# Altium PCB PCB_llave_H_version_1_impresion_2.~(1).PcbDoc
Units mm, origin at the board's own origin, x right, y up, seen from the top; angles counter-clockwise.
Board outline 85.85 x 71.63 mm, 2 copper layers (Top Layer, Bottom Layer); 118 components, 34 nets, 348 pads, 10 vias.
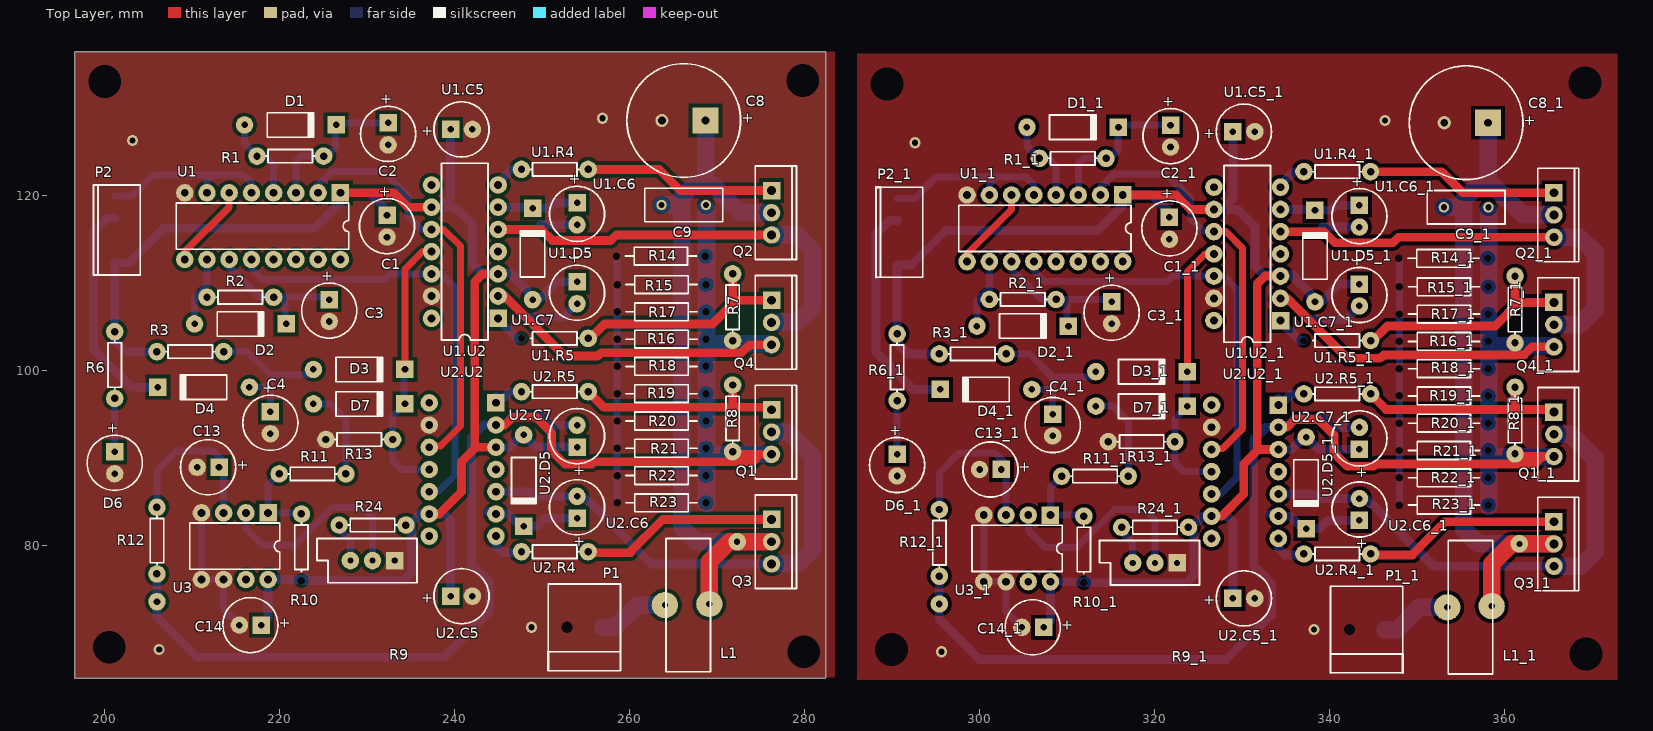
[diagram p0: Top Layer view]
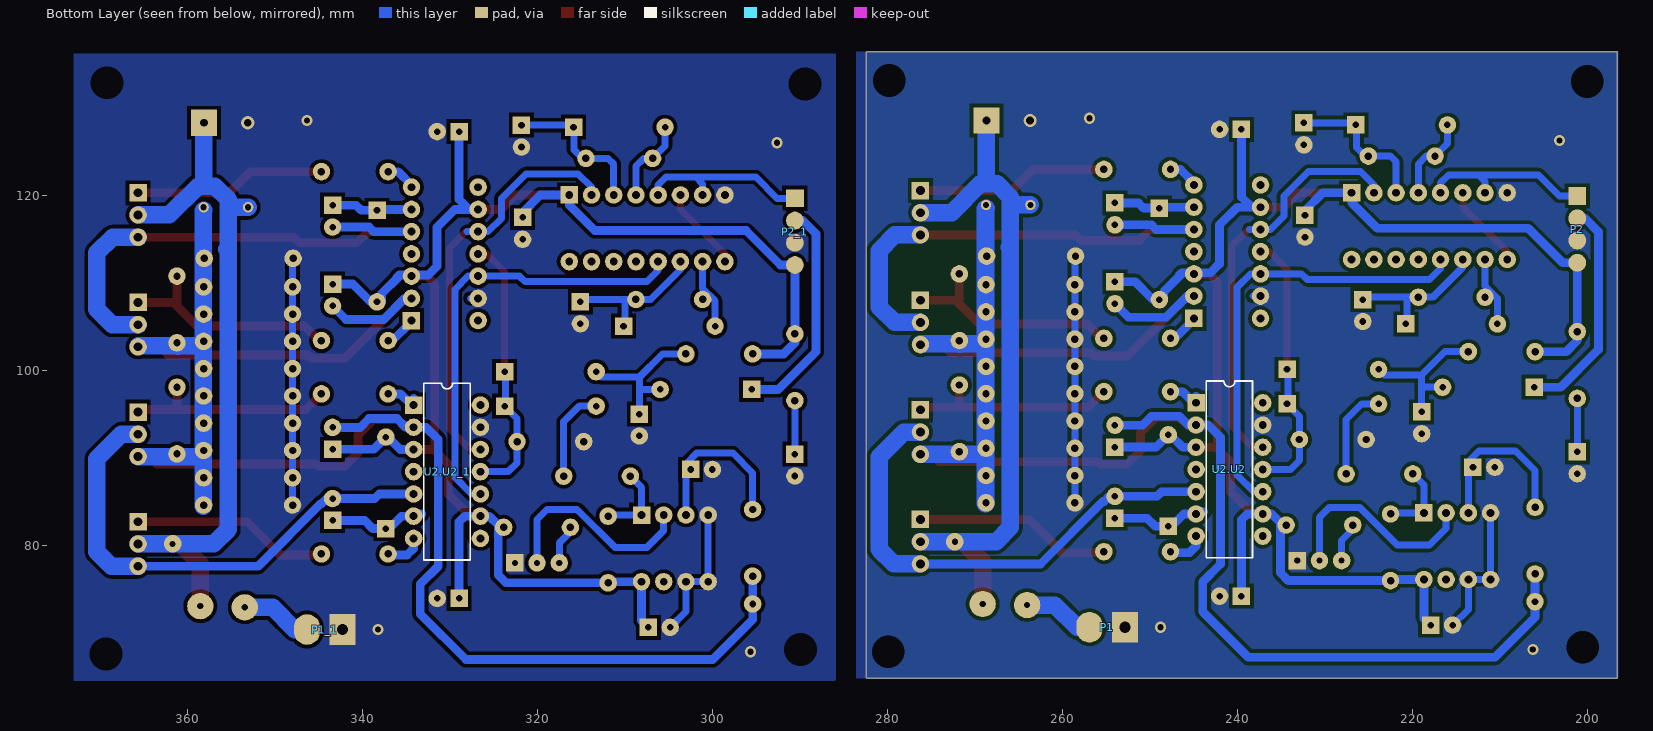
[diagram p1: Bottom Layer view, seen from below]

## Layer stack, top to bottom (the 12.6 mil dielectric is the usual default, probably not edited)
Top Layer: signal copper 0.0356
Dielectric: dielectric 0.32, FR-4, Dk 4.8
Bottom Layer: signal copper 0.0356

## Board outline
196.596,136.398 282.448,136.398 282.448,64.897 282.321,64.77 196.596,64.77

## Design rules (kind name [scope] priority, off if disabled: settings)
Clearance [All] p1: gap=0.4
ComponentClearance [All] p1: gap=0.254 collisioncheckmode=2 verticalgap=0.254
PlaneConnect [All] p1: planeconnectstyle=Direct reliefexpansion=0.508 reliefentries=4 reliefconductorwidth=0.254 reliefairgap=0.254
PolygonConnect [All] p1: connectstyle=Direct reliefconductorwidth=0.254 reliefentries=4 polygonreliefangle="90 Angle"
RoomDefinition U_4049_1 [InComponentClass('U_4049')] p1: confinementstyle=ConfineIn formatcopy=TRUE lockcomponents=FALSE outline 295.783,101.219 329.819,101.219 329.819,131.699 295.783,131.699
RoomDefinition Llave_H_esquema_1 [InComponentClass('Llave_H_esquema')] p2: confinementstyle=ConfineIn formatcopy=TRUE lockcomponents=FALSE outline 286.004,64.643 371.856,64.643 371.856,136.144 286.004,136.144
RoomDefinition U_Shutdown_1 [InComponentClass('U_Shutdown')] p3: confinementstyle=ConfineOut formatcopy=TRUE lockcomponents=FALSE outline 290.449,103.632 291.846,103.632 291.846,100.33 290.449,100.33
RoomDefinition U_INITShutdown_1 [InComponentClass('U_INITShutdown')] p4: confinementstyle=ConfineIn formatcopy=TRUE lockcomponents=FALSE outline 287.909,105.791 287.909,90.043 325.755,90.043 325.755,105.791
RoomDefinition U_Puente_H_1 [InComponentClass('U_Puente_H')] p5: confinementstyle=ConfineIn formatcopy=TRUE lockcomponents=FALSE outline 371.856,135.001 371.856,64.643 337.058,64.643 337.058,135.001
RoomDefinition U1_1 [InComponentClass('U1')] p6: confinementstyle=ConfineIn formatcopy=TRUE lockcomponents=FALSE outline 360.68,133.35 320.167,133.35 320.167,101.727 360.68,101.727
RoomDefinition U2_1 [InComponentClass('U2')] p7: confinementstyle=ConfineIn formatcopy=TRUE lockcomponents=FALSE outline 366.268,69.469 319.024,69.469 319.024,109.22 366.268,109.22
RoomDefinition U2 [InComponentClass('U2')] p8: confinementstyle=ConfineIn formatcopy=TRUE lockcomponents=FALSE outline 276.86,69.723 229.616,69.723 229.616,109.474 276.86,109.474
RoomDefinition U1 [InComponentClass('U1')] p9: confinementstyle=ConfineIn formatcopy=TRUE lockcomponents=FALSE outline 271.272,133.604 230.759,133.604 230.759,101.981 271.272,101.981
RoomDefinition U_Puente_H [InComponentClass('U_Puente_H')] p10: confinementstyle=ConfineIn formatcopy=TRUE lockcomponents=FALSE outline 282.448,135.255 282.448,64.897 247.65,64.897 247.65,135.255
RoomDefinition U_INITShutdown [InComponentClass('U_INITShutdown')] p11: confinementstyle=ConfineIn formatcopy=TRUE lockcomponents=FALSE outline 198.501,106.045 198.501,90.297 236.347,90.297 236.347,106.045
RoomDefinition U_Shutdown [InComponentClass('U_Shutdown')] p12: confinementstyle=ConfineOut formatcopy=TRUE lockcomponents=FALSE outline 201.041,103.886 202.438,103.886 202.438,100.584 201.041,100.584
RoomDefinition Llave_H_esquema [InComponentClass('Llave_H_esquema')] p13: confinementstyle=ConfineIn formatcopy=TRUE lockcomponents=FALSE outline 196.596,64.897 282.448,64.897 282.448,136.398 196.596,136.398
RoomDefinition U_4049 [InComponentClass('U_4049')] p14: confinementstyle=ConfineIn formatcopy=TRUE lockcomponents=FALSE outline 206.375,101.473 240.411,101.473 240.411,131.953 206.375,131.953
RoutingVias [All] p1: holewidth=0.711 width=1.27 viastyle="Through Hole" minholewidth=0.711 minwidth=1.27 maxholewidth=0.711 maxwidth=1.27
SolderMaskExpansion [All] p1: expansion=0.102
TestPointUsage [All] p1: valid=0 allowmultiple=FALSE
Testpoint [All] p1: side=15 testpointundercomponent=TRUE minsize=1.016 maxsize=2.54 preferedsize=1.524 minholesize=0 maxholesize=1.016 preferedholesize=0.813 testpointgrid=0.025 style=1023 order=0123456789
Width [All] p1: maxlimit=3 minlimit=0.8 preferedwidth=1
17 further rules are at their usual default settings.

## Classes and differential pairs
component class Llave_H_esquema: D6 P1 P2 R6
component class U_4049: C1 C2 C3 D1 D2 R1 R2 U1
component class U_Puente_H: C8 C9 L1 Q1 Q2 Q3 Q4 R7 R8
component class U_Shutdown: C13 C14 D7 R9 R10 R11 R12 R13 R14 R15 R16 R17 R18 R19 R20 R21 R22 R23 R24 U3
channel class IR2110: U1 U2
component class U_INITShutdown: C4 D3 D4 R3
component class U1: U1.C5 U1.C6 U1.C7 U1.D5 U1.R4 U1.R5 U1.U2 U_1_C5 U_1_C6 U_1_C7 U_1_D5 U_1_R4 U_1_R5 U_1_U2
component class U2: D5 U2.C5 U2.C6 U2.C7 U2.D5 U2.R4 U2.R5 U2.U2 U_2.D5 U_2_C5 U_2_C6 U_2_C7 U_2_R4 U_2_R5 U_2_U2

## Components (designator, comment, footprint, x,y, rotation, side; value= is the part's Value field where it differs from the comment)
C1 "Cap Pol1 0.1u" CAPPR2.5-6.3X5 232.283,116.459 r270 top
C1_1 "Cap Pol1 0.1u" CAPPR2.5-6.3X5 321.691,116.205 r270 top (schematic designator C1)
C2 "Cap Pol1" CAPPR2.5-6.3X5 232.41,127 r270 top
C2_1 "Cap Pol1" CAPPR2.5-6.3X5 321.818,126.746 r270 top (schematic designator C2)
C3 "Cap Pol1" CAPPR2.5-6.3X5 225.679,106.807 r270 top
C3_1 "Cap Pol1" CAPPR2.5-6.3X5 315.087,106.553 r270 top (schematic designator C3)
C4 "Cap Pol1 4.7u" CAPPR2.5-6.3X5 218.948,93.98 r270 top
C4_1 "Cap Pol1 4.7u" CAPPR2.5-6.3X5 308.356,93.726 r270 top (schematic designator C4)
C8 "Cap Pol1" CAPPR5-13X16 266.192,128.524 r180 top
C8_1 "Cap Pol1" CAPPR5-13X16 355.6,128.27 r180 top (schematic designator C8)
C9 "Cap" RAD-0.2 266.192,118.872 r180 top
C9_1 "Cap" RAD-0.2 355.6,118.618 r180 top (schematic designator C9)
C13 "Cap Pol1 4.7u" CAPPR2.5-6.3X5 211.836,88.9 r180 top
C13_1 "Cap Pol1 4.7u" CAPPR2.5-6.3X5 301.244,88.646 r180 top (schematic designator C13)
C14 "Cap Pol1 0.1u" CAPPR2.5-6.3X5 216.662,70.866 r180 top
C14_1 "Cap Pol1 0.1u" CAPPR2.5-6.3X5 306.07,70.612 r180 top (schematic designator C14)
D1 "Diode1" DO-204AL 221.234,128.016 r0 top
D1_1 "Diode1" DO-204AL 310.642,127.762 r0 top (schematic designator D1)
D2 "Diode1" DO-204AL 215.519,105.283 r0 top
D2_1 "Diode1" DO-204AL 304.927,105.029 r0 top (schematic designator D2)
D3 "Diode1" DO-204AL 229.108,100.076 r0 top
D3_1 "Diode1" DO-204AL 318.516,99.822 r0 top (schematic designator D3)
D4 "Diode1" DO-204AL 211.328,98.044 r180 top
D4_1 "Diode1" DO-204AL 300.736,97.79 r180 top (schematic designator D4)
D6 "LED0" CAPPR2.5-6.3X5 201.168,89.408 r270 top
D6_1 "LED0" CAPPR2.5-6.3X5 290.576,89.154 r270 top (schematic designator D6)
D7 "Diode1" DO-204AL 229.108,96.139 r0 top
D7_1 "Diode1" DO-204AL 318.516,95.885 r0 top (schematic designator D7)
L1 "Inductor" bobina_Choque 264.16,75.692 r270 top
L1_1 "Inductor" bobina_Choque 353.568,75.438 r270 top (schematic designator L1)
P1 "Header 2" pwheader1x2 255.016,70.612 r0 top
P1_1 "Header 2" pwheader1x2 344.424,70.358 r0 top (schematic designator P1)
P2 "Header 4" HDR1X5 193.548,112.268 r270 top
P2_1 "Header 4" HDR1X5 282.956,112.014 r270 top (schematic designator P2)
Q1 "IRF3205" TO-220AB 276.225,80.391 r270 top
Q1_1 "IRF3205" TO-220AB 365.633,80.137 r270 top (schematic designator Q1)
Q2 "IRF3205" TO-220AB 276.225,117.983 r270 top
Q2_1 "IRF3205" TO-220AB 365.633,117.729 r270 top (schematic designator Q2)
Q3 "IRF3205" TO-220AB 276.225,92.922 r270 top
Q3_1 "IRF3205" TO-220AB 365.633,92.668 r270 top (schematic designator Q3)
Q4 "IRF3205" TO-220AB 276.225,105.452 r270 top
Q4_1 "IRF3205" TO-220AB 365.633,105.198 r270 top (schematic designator Q4)
R1 "18k" AXIAL-0.3#1 221.234,124.46 r180 top
R1_1 "18k" AXIAL-0.3#1 310.642,124.206 r180 top (schematic designator R1)
R2 "18k" AXIAL-0.3#1 215.519,108.331 r0 top
R2_1 "18k" AXIAL-0.3#1 304.927,108.077 r0 top (schematic designator R2)
R3 "4.7k" AXIAL-0.3#1 209.804,102.108 r180 top
R3_1 "4.7k" AXIAL-0.3#1 299.212,101.854 r180 top (schematic designator R3)
R6 "1.2k" AXIAL-0.3#1 201.168,100.584 r90 top
R6_1 "1.2k" AXIAL-0.3#1 290.576,100.33 r90 top (schematic designator R6)
R7 "6.8" AXIAL-0.3#1 271.78,107.188 r90 top
R7_1 "6.8" AXIAL-0.3#1 361.188,106.934 r90 top (schematic designator R7)
R8 "6.8" AXIAL-0.3#2 271.78,94.488 r90 top
R8_1 "6.8" AXIAL-0.3#2 361.188,94.234 r90 top (schematic designator R8)
R9 "RPot" VR5 230.632,78.232 r180 top
R9_1 "RPot" VR5 320.04,77.978 r180 top (schematic designator R9)
R10 "3.3k" AXIAL-0.3#3 222.504,79.756 r270 top
R10_1 "3.3k" AXIAL-0.3#3 311.912,79.502 r270 top (schematic designator R10)
R11 "470" AXIAL-0.3#1 223.774,88.138 r0 top
R11_1 "470" AXIAL-0.3#1 313.182,87.884 r0 top (schematic designator R11)
R12 "6.8" AXIAL-0.3#1 205.994,80.518 r90 top locked
R12_1 "6.8" AXIAL-0.3#1 295.402,80.264 r90 top locked (schematic designator R12)
R13 "10k" AXIAL-0.3#1 229.108,92.075 r0 top
R13_1 "10k" AXIAL-0.3#1 318.516,91.821 r0 top (schematic designator R13)
R14 "Res2" AXIAL-0.4#1 263.585,113.03 r0 top
R14_1 "Res2" AXIAL-0.4#1 352.993,112.776 r0 top (schematic designator R14)
R15 "Res2" AXIAL-0.4#1 263.652,109.774 r0 top
R15_1 "Res2" AXIAL-0.4#1 353.06,109.52 r0 top (schematic designator R15)
R16 "Res2" AXIAL-0.4#1 263.652,106.657 r0 top
R16_1 "Res2" AXIAL-0.4#1 353.06,106.403 r0 top (schematic designator R16)
R17 "Res2" AXIAL-0.4#1 263.652,103.539 r0 top
R17_1 "Res2" AXIAL-0.4#1 353.06,103.285 r0 top (schematic designator R17)
R18 "Res2" AXIAL-0.4#1 263.652,100.422 r0 top
R18_1 "Res2" AXIAL-0.4#1 353.06,100.168 r0 top (schematic designator R18)
R19 "Res2" AXIAL-0.4#1 263.652,97.305 r0 top
R19_1 "Res2" AXIAL-0.4#1 353.06,97.051 r0 top (schematic designator R19)
R20 "Res2" AXIAL-0.4#2 263.652,94.188 r0 top
R20_1 "Res2" AXIAL-0.4#2 353.06,93.934 r0 top (schematic designator R20)
R21 "Res2" AXIAL-0.4#2 263.652,91.07 r0 top
R21_1 "Res2" AXIAL-0.4#2 353.06,90.816 r0 top (schematic designator R21)
R22 "Res2" AXIAL-0.4#2 263.652,87.953 r0 top
R22_1 "Res2" AXIAL-0.4#2 353.06,87.699 r0 top (schematic designator R22)
R23 "Res2" AXIAL-0.4#2 263.652,84.836 r0 top
R23_1 "Res2" AXIAL-0.4#2 353.06,84.582 r0 top (schematic designator R23)
R24 "6.8" AXIAL-0.3#1 230.632,82.296 r0 top
R24_1 "6.8" AXIAL-0.3#1 320.04,82.042 r0 top (schematic designator R24)
U1 "MC54HC4049J" 620-09 218.059,116.459 r180 top
U1.C5 "Cap Pol1 4.7u" CAPPR2.5-6.3X5 240.792,127.508 r0 top (schematic designator C5)
U1.C5_1 "Cap Pol1 4.7u" CAPPR2.5-6.3X5 330.2,127.254 r0 top (schematic designator C5)
U1.C6 "Cap Pol1" CAPPR2.5-6.3X5 254,117.856 r270 top (schematic designator C6)
U1.C6_1 "Cap Pol1" CAPPR2.5-6.3X5 343.408,117.602 r270 top (schematic designator C6)
U1.C7 "Cap Pol1" CAPPR2.5-6.3X5 254,108.839 r270 top (schematic designator C7)
U1.C7_1 "Cap Pol1" CAPPR2.5-6.3X5 343.408,108.585 r270 top (schematic designator C7)
U1.D5 "Diode" DO-204AL 248.92,113.284 r90 top (schematic designator D5)
U1.D5_1 "Diode" DO-204AL 338.328,113.03 r90 top (schematic designator D5)
U1.R4 "10" AXIAL-0.3#1 251.46,122.936 r0 top (schematic designator R4)
U1.R4_1 "10" AXIAL-0.3#1 340.868,122.682 r0 top (schematic designator R4)
U1.R5 "10" AXIAL-0.3#4 251.46,103.632 r0 top (schematic designator R5)
U1.R5_1 "10" AXIAL-0.3#4 340.868,103.378 r0 top (schematic designator R5)
U1.U2 "IR2110" PDIP14 241.173,113.538 r90 top (schematic designator U2)
U1.U2_1 "IR2110" PDIP14 330.581,113.284 r90 top (schematic designator U2)
U1_1 "MC54HC4049J" 620-09 307.467,116.205 r180 top (schematic designator U1)
U2.C5 "Cap Pol1 4.7u" CAPPR2.5-6.3X5 240.792,74.168 r0 top (schematic designator C5)
U2.C5_1 "Cap Pol1 4.7u" CAPPR2.5-6.3X5 330.2,73.914 r0 top (schematic designator C5)
U2.C6 "Cap Pol1" CAPPR2.5-6.3X5 254,84.328 r90 top (schematic designator C6)
U2.C6_1 "Cap Pol1" CAPPR2.5-6.3X5 343.408,84.074 r90 top (schematic designator C6)
U2.C7 "Cap Pol1" CAPPR2.5-6.3X5 254,92.456 r90 top (schematic designator C7)
U2.C7_1 "Cap Pol1" CAPPR2.5-6.3X5 343.408,92.202 r90 top (schematic designator C7)
U2.D5 "Diode" DO-204AL 247.904,87.376 r270 top (schematic designator D5)
U2.D5_1 "Diode" DO-204AL 337.312,87.122 r270 top (schematic designator D5)
U2.R4 "10" AXIAL-0.3#1 251.46,79.248 r0 top (schematic designator R4)
U2.R4_1 "10" AXIAL-0.3#1 340.868,78.994 r0 top (schematic designator R4)
U2.R5 "10" AXIAL-0.3#1 251.46,97.536 r0 top (schematic designator R5)
U2.R5_1 "10" AXIAL-0.3#1 340.868,97.282 r0 top (schematic designator R5)
U2.U2 "IR2110" PDIP14 240.919,88.646 r270 bottom (schematic designator U2)
U2.U2_1 "IR2110" PDIP14 330.327,88.392 r270 bottom (schematic designator U2)
U3 "LM393N" 626-05 214.884,79.883 r180 top
U3_1 "LM393N" 626-05 304.292,79.629 r180 top (schematic designator U3)

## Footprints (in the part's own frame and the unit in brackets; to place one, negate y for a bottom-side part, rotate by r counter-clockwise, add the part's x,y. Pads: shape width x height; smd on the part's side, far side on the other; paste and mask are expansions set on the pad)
620-09 [mm] "DIP; 16 Leads; Row Spacing 7.62 mm; Pitch 2.54 mm"
  rect 2x2 hole 0.9: 1(-8.89,-3.81)
  round 2 hole 0.9: 2(-6.35,-3.81) 3(-3.81,-3.81) 4(-1.27,-3.81) 5(1.27,-3.81) 6(3.81,-3.81) 7(6.35,-3.81) 8(8.89,-3.81) 9(8.89,3.81) 10(6.35,3.81) 11(3.81,3.81) 12(1.27,3.81) 13(-1.27,3.81) 14(-3.81,3.81) 15(-6.35,3.81) 16(-8.89,3.81)
  silkscreen extent -9.85,-2.65 9.85,2.65
626-05 [mm] "DIP; 8 Leads; Row Spacing 7.62 mm; Pitch 2.54 mm"
  rect 2x2 hole 0.9: 1(-3.81,-3.81)
  round 2 hole 0.9: 2(-1.27,-3.81) 3(1.27,-3.81) 4(3.81,-3.81) 5(3.81,3.81) 6(1.27,3.81) 7(-1.27,3.81) 8(-3.81,3.81)
  silkscreen extent -5.15,-2.65 5.15,2.65
AXIAL-0.3#1 [mm] "Resistor; 2 Leads"
  round 2 hole 0.85: 1(-3.81,0) 2(3.81,0)
  silkscreen extent -2.77,-0.76 2.77,0.76
AXIAL-0.3#2 [mm] "Resistor; 2 Leads"
  round 2 hole 0.85 paste+0 mask+0.102: 1(-3.81,0)
  round 2 hole 0.85: 2(3.81,0)
  silkscreen extent -2.77,-0.76 2.77,0.76
AXIAL-0.3#3 [mm] "Resistor; 2 Leads"
  round 2 hole 0.85: 1(-3.81,0)
  round 0 / inner round 0 / far side round 2 hole 0.85: 2(3.81,0)
  silkscreen extent -2.77,-0.76 2.77,0.76
AXIAL-0.3#4 [mm] "Resistor; 2 Leads"
  round 0 / inner round 0 / far side round 2 hole 0.85: 1(-3.81,0)
  round 2 hole 0.85: 2(3.81,0)
  silkscreen extent -2.77,-0.76 2.77,0.76
AXIAL-0.4#1 [mm] "Resistor; 2 Leads"
  round 0 / inner round 0 / far side round 2 hole 0.85: 1(-5.08,0) 2(5.08,0)
  silkscreen extent -4.06,-1.02 4.06,1.02
AXIAL-0.4#2 [mm] "Resistor; 2 Leads"
  round 0 / inner round 0 / far side round 2 hole 0.85: 1(-5.08,0)
  round 0 / inner round 0 / far side round 2 hole 0.85 unplated: 2(5.08,0)
  silkscreen extent -4.06,-1.02 4.06,1.02
bobina_Choque [mm]
  round 3 hole 0.7: 1(2.54,-0.127) 2(2.413,4.953)
  silkscreen extent -5.08,0 10.16,5.08
CAPPR2.5-6.3X5 [mm] "Capacitor, Electrolytic, Radial; Body 6.3 x 5 mm (Dia.xH typ); Pin Spacing 2.5 mm (typ)"
  rect 2x2 hole 0.75: 1(-1.25,0)
  round 2 hole 0.75: 2(1.25,0)
  silkscreen extent -3.15,-3.15 3.15,3.15
CAPPR5-13X16 [mm] "Capacitor, Electrolytic, Radial; Body 13 x 16 mm (Dia.xH typ); Pin Spacing 5 mm (typ)"
  rect 3x3 hole 0.9: 1(-2.5,0)
  round 1.5 hole 0.9: 2(2.5,0)
  silkscreen extent -6.5,-6.5 6.5,6.5
DO-204AL [mm] "Diode, Axial; Body 5.2 x 2.7 mm (LxDia. max), Lead Dia. 0.86 mm (max)"
  round 2 hole 0.75: 1(-5.23,0)
  rect 2x2 hole 0.75: 2(5.23,0)
  silkscreen extent -2.65,-1.4 2.75,1.4
HDR1X5 [mil]
  rect 80x80 smd far side: 1(-300,300)
  round 80 smd far side: 2(-200,300) 3(-100,300) 4(0,300)
  silkscreen extent -350,205 55,415
PDIP14 [mm] "DIP; 14 Leads; Row Spacing 7.62 mm; Pitch 2.54 mm"
  rect 2x2 hole 0.9: 1(-7.62,-3.81)
  round 2 hole 0.9: 2(-5.08,-3.81) 3(-2.54,-3.81) 4(0,-3.81) 5(2.54,-3.81) 6(5.08,-3.81) 7(7.62,-3.81) 8(7.62,3.81) 9(5.08,3.81) 10(2.54,3.81) 11(0,3.81) 12(-2.54,3.81) 13(-5.08,3.81) 14(-7.62,3.81)
  silkscreen extent -10.1,-2.65 10.1,2.65
pwheader1x2 [mm]
  round 0 / inner round 0 / far side rect 3x3.5 hole 1.3: 1(-2.159,0)
  oval 3x3.5 smd far side: 2(1.905,0)
  silkscreen extent -4.32,-4.95 3.94,4.95
RAD-0.2 [mm] "Jumper Wire; 2 Leads"
  round 1.2 hole 0.7: 1(-2.54,0) 2(2.54,0)
  silkscreen extent -4.44,-1.91 4.44,1.91
TO-220AB [mm] "TO, Thru-Hole, Vertical, Heatsink Mounted; 3 In-Line Leads; Pitch 2.54 mm"
  rect 2x2 hole 1: 1(-2.54,0)
  round 2 hole 1: 2(0,0) 3(2.54,0)
  silkscreen extent -5.35,-1.85 5.35,2.85
VR5 [mm] "Potentiometer; 3 Leads"
  rect 2x2 hole 0.7: 1(-2.54,0)
  round 2 hole 0.7: 2(2.54,0) 3(0,0)
  silkscreen extent -5.08,-2.54 6.35,2.54

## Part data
C1 C1_1 C4 C4_1 C14 C14_1 U1.C5 U1.C5_1 U2.C5 U2.C5_1: library part "Cap Pol1", "Polarized Capacitor (Radial)"
C2 C2_1 C3 C3_1 C8 C8_1 U1.C6 U1.C6_1 U1.C7 U1.C7_1 U2.C6 U2.C6_1 U2.C7 U2.C7_1: "Polarized Capacitor (Radial)"
C9 C9_1: "Capacitor"
C13 C13_1: library part "Cap Pol1", "Polarized 16V"
D1 D1_1 D2 D2_1: library part Diode, "1N4148"
D3 D3_1 D4 D4_1 D7 D7_1: library part Diode, "1n4148"
D6 D6_1: "Typical INFRARED GaAs LED"
P1 P1_1: "Header, 2-Pin"
P2 P2_1: "Header, 4-Pin"
Q1 Q1_1 Q2 Q2_1 Q3 Q3_1 Q4 Q4_1: "HEXFET Power MOSFET"
R1 R1_1 R2 R2_1 R3 R3_1 R6 R6_1 R7 R7_1 R8 R8_1 R24 R24_1 U1.R4 U1.R4_1 U1.R5 U1.R5_1 U2.R4 U2.R4_1 U2.R5 U2.R5_1: library part Res2, "Resistor"
R9 R9_1: "Potenciomentro multivuelta"
R10 R10_1 R11 R11_1 R12 R12_1 R13 R13_1: library part Res2, "metal film 1/2 W"
R14 R14_1 R15 R15_1 R16 R16_1 R17 R17_1 R18 R18_1 R19 R19_1 R20 R20_1 R21 R21_1 R22 R22_1 R23 R23_1: "metal film 1W"
U1 U1_1: "Hex Inverting Buffer/Logic-Level Down Converter"
U1.D5 U1.D5_1 U2.D5 U2.D5_1: "1N5819"
U1.U2 U1.U2_1 U2.U2 U2.U2_1: "High and Low Side Driver"
U3 U3_1: "Dual Comparator"

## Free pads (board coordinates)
  round 1.524 hole 3.75: 0(200.025,132.969) 0(200.533,68.326) 0(279.781,133.096) 0(279.908,67.818) 0(289.433,132.715) 0(289.941,68.072) 0(369.189,132.842) 0(369.316,67.564)
  round 2 hole 0.762: 1(205.994,73.533) 1(295.402,73.279)

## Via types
v1: diameter 1.27, hole 0.711, Top Layer to Bottom Layer, 8 vias
v2: diameter 2, hole 0.711, Top Layer to Bottom Layer, 2 vias

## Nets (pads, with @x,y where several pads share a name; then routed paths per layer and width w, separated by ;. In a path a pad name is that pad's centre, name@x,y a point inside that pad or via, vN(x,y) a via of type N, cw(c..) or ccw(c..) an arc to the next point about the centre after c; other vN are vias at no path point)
COMMON: C9.1 pad.1@205.994,73.533 Q3.3 Q4.3 R7.1 R8.1 R12.1 R14.2 R15.2 R16.2 R17.2 R18.2 R19.2 R20.2 R21.2 R22.2 R23.2 U1.C7.2 U1.U2.2 U2.C7.2 U2.U2.2 | length 218.7
  Top Layer w1: U2.U2.2 245.745,93.726 246.634,94.615 249.301,94.615 251.079,92.837 251.079,90.805 252.603,89.281 255.646,89.281 255.9,89.535 274.066,89.535 274.913,90.382 ; U1.U2.2 245.745,108.458 252.603,101.6 256.286,101.6 256.413,101.727 256.54,101.727 256.794,101.981 272.796,101.981 273.727,102.912 Q4.3 ; R8.1@271.78,90.382 Q3.3
  Bottom Layer w1: R12.1 205.994,71.755 210.566,67.183 238.76,67.183 243.967,72.39 243.967,75.819 241.935,77.851 241.935,92.329 243.332,93.726 245.633,93.726 246.629,94.722 249.829,94.722 250.845,93.706 U2.C7.2 ; U1.U2.2 245.745,108.458 248.158,106.045 252.456,106.045 U1.C7.2 ; R7.1@271.713,102.997 271.798,102.912 Q4.3
  Bottom Layer w2: C9.1@268.732,118.526 268.792,118.465 R23.2@268.792,84.709 ; R21.2@268.792,90.382 Q3.3 ; R17.2@268.792,103.031 Q4.3@276.191,103.031 ; R7.1@271.713,102.965 R7.1@271.78,103.031
GND: C1.2 C2.2 C3.2 C4.2 C8.2 C13.2 C14.2 D6.2 P1.1 P2.3 pad.0@200.025,132.969 pad.0@200.533,68.326 pad.0@279.781,133.096 pad.0@279.908,67.818 R9.1 R13.1 R14.1 R15.1 R16.1 R17.1 R18.1 R19.1 R20.1 R21.1 R22.1 R23.1 U1.8 U1.C5.2 U1.U2.13 U2.C5.2 U2.U2.13 U3.4 U3.5 U3.6 | length 45.2
  Top Layer w0.8: U3.5 211.094,76.093 U3.5@211.074,76.113 ; U3.6@213.594,76.093 U3.6
  Bottom Layer w0.8: U3.5 U3.4 ; U3.5@211.094,76.093 U3.6@213.594,76.093 ; U3.6 213.614,72.664 C14.2 ; U1.U2.13 U1.U2.13@238.252,108.458 ; R23.1 R14.1@258.572,112.963
  other v1: 206.248,68.072 248.793,70.612 203.2,126.238 256.921,128.778
HO1: Q2.1 U1.R4.2 | length 22
  Top Layer w1: U1.R4.2 263.398,122.936 265.811,120.523 Q2.1
HO2: Q1.1 U2.R4.2 | length 22
  Top Layer w1: U2.R4.2@255.905,79.121 260.096,79.121 ; 259.969,79.121 263.779,82.931 Q1.1
IN_SD: D4.2 P2.2 | length 25.6
  Bottom Layer w1: P2.2 200.279,117.348 198.755,115.824 198.755,102.362 203.073,98.044 D4.2
LO1: Q4.1 R7.2 U1.R5.2 | length 26.4
  Top Layer w1: U1.R5.2 255.524,103.632 257.175,105.283 269.494,105.283 272.203,107.992 Q4.1 ; R7.2@271.78,111.252 271.78,107.592 271.791,107.58
LO2: Q3.1 R8.2 U2.R5.2 | length 24.5
  Top Layer w1: U2.R5.2@255.778,97.536 255.778,97.028 257.048,95.758 275.929,95.758 Q3.1 ; R8.2@271.526,98.679 R8.2@271.78,98.425 ; 271.78,95.758 R8.2
MOTOR+: Q2.3 Q4.2 U1.C6.2 U1.U2.5 | length 58.6
  Top Layer w1: U1.U2.5 249.936,116.078 251.206,114.808 257.836,114.808 258.471,115.443 Q2.3
  Bottom Layer w1: U1.U2.5 249.301,116.078 249.829,116.606 U1.C6.2
  Bottom Layer w2: Q4.2 279.188,105.452 280.924,107.188 280.924,113.665 279.146,115.443 Q2.3
MOTOR-: Q1.3 Q3.2 U2.C6.2 U2.U2.5 | length 56.8
  Bottom Layer w1: U2.U2.5 248.666,86.106 249.194,85.578 254.655,85.578 255.255,84.978 255.382,84.978 262.509,77.851 Q1.3
  Bottom Layer w2: Q1.3 279.273,77.851 280.924,79.502 280.924,90.128 278.13,92.922 Q3.2
NetC2_1: C2.1 D1.2 R1.1 U1.3 | length 17.4
  Bottom Layer w0.8: U1.3 221.869,123.825 222.504,124.46 225.425,124.46 226.403,125.438 226.403,127.955 226.698,128.25 C2.1
NetC3_1: C3.1 D2.2 R2.2 U1.11 | length 17
  Bottom Layer w0.8: U1.11 214.249,111.76 217.678,108.331 225.405,108.331 C3.1 ; 220.599,108.331 220.599,105.433 D2.2
NetC4_1: C4.1 D3.1 D4.1 R3.1 | length 18.2
  Bottom Layer w0.8: R3.1 216.281,102.108 218.948,99.441 ; D4.1 218.948,98.044 ; C4.1 218.948,99.441 ; D3.1 223.243,99.441 218.948,99.441
NetC13_1: C13.1 R12.2 U3.3 | length 19.1
  Bottom Layer w0.8: R12.2 205.994,88.519 208.24,90.765 212.384,90.765 213.614,89.535 U3.3
NetD1_1: D1.1 R1.2 U1.4 | length 9.7
  Bottom Layer w0.8: D1.1 216.004,125.88 R1.2 218.44,124.46 219.329,123.571 U1.4
NetD2_1: D2.1 R2.1 U1.10 | length 8
  Bottom Layer w0.8: D2.1 210.289,108.181 211.709,109.601 U1.10
NetD6_1: D6.1 R6.1 | length 6.1
  Bottom Layer w0.8: D6.1 R6.1
NetD7_1: D7.1 R11.2 | length 10.7
  Bottom Layer w0.8: D7.1 225.806,96.139 227.584,94.361 R11.2
NetR9_2: R9.2 R24.1 | length 4.8
  Bottom Layer w0.8: R24.1@226.949,82.55 226.949,81.661 228.092,80.518 R9.2
NetR9_3: R9.3 U3.2 | length 24.3
  Bottom Layer w0.8: U3.2 216.154,81.915 218.059,80.01 221.742,80.01 226.06,84.328 229.489,84.328 230.632,83.185 R9.3
NetR10_1: R10.1 R11.1 U3.1 | length 9.5
  Bottom Layer w0.8: R11.1 218.694,86.868 U3.1 222.504,83.693 R10.1@223.012,83.185
NetU1.C6_1: U1.C6.1 U1.D5.2 U1.U2.6 | length 9.8
  Bottom Layer w1: U1.U2.6 248.308,118.618 248.412,118.514 250.721,118.514 251.313,119.106 U1.C6.1 ; U1.D5.2@248.943,118.872 U1.D5.2@249.301,118.514
NetU1.R4_1: U1.R4.1 U1.U2.7 | length 3.8
  Bottom Layer w1: U1.U2.7 244.983,121.412 246.507,122.936 U1.R4.1@247.904,122.936
NetU1.R5_1: U1.R5.1 U1.U2.1 | length 3.7
  Bottom Layer w1: U1.U2.1 244.983,105.791 247.142,103.632 U1.R5.1
NetU1_6: U1.6 U1.9 | length 9.9
  Top Layer w0.8: U1.9 209.169,113.538 214.249,118.618 U1.6
  Bottom Layer w0.8: U1.9 U1.9@209.169,112.776
NetU2.C6_1: U2.C6.1 U2.D5.2 U2.U2.6 | length 10.8
  Bottom Layer w1: U2.U2.6@243.84,83.82 U2.U2.6@244.602,83.82 ; U2.U2.6 246.126,83.566 U2.D5.2@247.673,82.019 ; U2.D5.2 249.405,82.146 250.337,83.078 U2.C6.1
NetU2.R4_1: U2.R4.1 U2.U2.7 | length 4.9
  Bottom Layer w1: U2.U2.7 244.729,79.883 245.491,79.121 U2.R4.1@248.158,79.121
NetU2.R5_1: U2.R5.1 U2.U2.1 | length 4.7
  Bottom Layer w1: U2.U2.1@244.729,97.028 U2.U2.1 244.983,96.266 246.253,97.536 U2.R5.1@248.158,97.536
PWM: P2.1 U1.5 U1.7 | length 20.5
  Bottom Layer w0.8: P2.1 203.2,119.888 205.613,122.301 215.9,122.301 216.789,121.412 U1.5 ; U1.7 211.709,121.539 212.471,122.301
SD: D3.2 D7.2 R13.2 U1.U2.11 U2.U2.11 | length 31.1
  Top Layer w0.8: D3.2 234.338,111.529 236.347,113.538 U1.U2.11
  Bottom Layer w0.8: D7.2@234.241,96.042 234.241,99.979 D3.2 ; D7.2 232.918,94.719 232.918,89.662 233.934,88.646 U2.U2.11
U1.HIN: U1.2 U1.U2.10 U2.U2.12 | length 48.9
  Top Layer w0.8: U2.U2.12@237.236,91.313 238.379,91.313 240.665,93.599 240.665,114.173 238.76,116.078 U1.U2.10
  Bottom Layer w0.8: U1.2 224.409,121.158 225.933,122.682 231.902,122.682 234.696,119.888 234.696,117.602 236.22,116.078 238.633,116.078
U1.LIN: U1.12 U1.U2.12 U2.U2.10 | length 50.9
  Bottom Layer w0.8: U1.12 216.789,111.633 218.059,110.363 232.029,110.363 232.664,110.998 238.506,110.998 240.03,109.474 240.03,88.011 238.125,86.106 U2.U2.10
VCC_MOTOR: L1.1 P1.2 | length 8.2
  Bottom Layer w2: P1.2 258.318,70.612 260.858,73.152 L1.1
VCC_MOTOR_FILTRADO: C8.1 C9.2 L1.2 Q1.2 Q2.2 | length 83.3
  Top Layer w2: L1.2 269.113,78.105 271.399,80.391 Q1.2
  Bottom Layer w2: C9.2 265.811,118.872 265.938,118.745 ; 265.938,113.919 266.065,114.046 ; 268.692,121.579 C8.1 ; Q1.2 267.589,80.391 265.938,82.042 265.938,119.761 267.462,121.285 269.367,121.285 272.669,117.983 Q2.2
  other v2: 272.288,80.391
VDD: C1.1 C14.1 P2.4 R3.2 R6.2 R10.2 R24.2 U1.1 U1.C5.1 U1.C7.1 U1.D5.1 U1.U2.3 U1.U2.9 U2.C5.1 U2.C7.1 U2.D5.1 U2.U2.3 U2.U2.9 U3.8 | length 184.4
  Top Layer w0.8: C14.1 C14.1@217.912,71.481 ; U3.8@218.567,76.327 218.694,76.2 U3.8
  Top Layer w1: U1.1 233.045,120.269 234.696,118.618 U1.U2.9 ; U2.U2.9 238.252,83.566 240.792,86.106 240.792,89.535 242.443,91.186 U2.U2.3 ; 242.316,91.059 242.316,110.109 243.205,110.998 U1.U2.3
  Bottom Layer w0.8: R10.2@222.994,76.309 R10.2@223.012,76.292 ; C1.1 C1.1@232.283,118.11
  Bottom Layer w1: R3.2 202.438,102.108 201.168,103.378 P2.4 202.819,112.268 206.756,116.205 224.028,116.205 226.949,119.126 U1.1 230.251,120.269 232.283,118.237 C1.1 ; C14.1 218.694,71.648 U3.8 R10.2@222.758,76.073 ; R10.2 234.188,75.946 235.077,76.835 235.077,82.55 236.093,83.566 238.887,83.566 239.542,82.911 U2.C5.1 ; U1.U2.9 240.03,118.618 242.062,116.586 242.062,112.141 243.078,111.125 246.38,111.125 246.634,110.871 ; 238.379,118.618 239.542,119.781 U1.C5.1 ; U2.U2.3 246.253,91.186 U2.D5.1@247.546,92.479 ; 246.38,110.998 248.412,108.966 U1.D5.1@248.412,108.054 ; U2.D5.1 247.904,92.583 249.281,91.206 U2.C7.1 ; U1.D5.1 249.659,108.054 251.694,110.089 U1.C7.1
pads on no net: C1_1.1 C1_1.2 C2_1.1 C2_1.2 C3_1.1 C3_1.2 C4_1.1 C4_1.2 C8_1.1 C8_1.2 C9_1.1 C9_1.2 C13_1.1 C13_1.2 C14_1.1 C14_1.2 D1_1.1 D1_1.2 D2_1.1 D2_1.2 D3_1.1 D3_1.2 D4_1.1 D4_1.2 D6_1.1 D6_1.2 D7_1.1 D7_1.2 L1_1.1 L1_1.2 P1_1.1 P1_1.2 P2_1.1 P2_1.2 P2_1.3 P2_1.4 Q1_1.1 Q1_1.2 Q1_1.3 Q2_1.1 Q2_1.2 Q2_1.3 Q3_1.1 Q3_1.2 Q3_1.3 Q4_1.1 Q4_1.2 Q4_1.3 R1_1.1 R1_1.2 R2_1.1 R2_1.2 R3_1.1 R3_1.2 R6_1.1 R6_1.2 R7_1.1 R7_1.2 R8_1.1 R8_1.2 R9_1.1 R9_1.2 R9_1.3 R10_1.1 R10_1.2 R11_1.1 R11_1.2 R12_1.1 R12_1.2 R13_1.1 R13_1.2 R14_1.1 R14_1.2 R15_1.1 R15_1.2 R16_1.1 R16_1.2 R17_1.1 R17_1.2 R18_1.1 R18_1.2 R19_1.1 R19_1.2 R20_1.1 R20_1.2 R21_1.1 R21_1.2 R22_1.1 R22_1.2 R23_1.1 R23_1.2 R24_1.1 R24_1.2 U1.13 U1.14 U1.15 U1.16 U1.C5_1.1 U1.C5_1.2 U1.C6_1.1 U1.C6_1.2 U1.C7_1.1 U1.C7_1.2 U1.D5_1.1 U1.D5_1.2 U1.R4_1.1 U1.R4_1.2 U1.R5_1.1 U1.R5_1.2 U1.U2.4 U1.U2.8 U1.U2.14 U1.U2_1.1 U1.U2_1.2 U1.U2_1.3 U1.U2_1.4 U1.U2_1.5 U1.U2_1.6 U1.U2_1.7 U1.U2_1.8 U1.U2_1.9 U1.U2_1.10 U1.U2_1.11 U1.U2_1.12 U1.U2_1.13 U1.U2_1.14 U1_1.1 U1_1.2 U1_1.3 U1_1.4 U1_1.5 U1_1.6 U1_1.7 U1_1.8 U1_1.9 U1_1.10 U1_1.11 U1_1.12 U1_1.13 U1_1.14 U1_1.15 U1_1.16 U2.C5_1.1 U2.C5_1.2 U2.C6_1.1 U2.C6_1.2 U2.C7_1.1 U2.C7_1.2 U2.D5_1.1 U2.D5_1.2 U2.R4_1.1 U2.R4_1.2 U2.R5_1.1 U2.R5_1.2 U2.U2.4 U2.U2.8 U2.U2.14 U2.U2_1.1 U2.U2_1.2 U2.U2_1.3 U2.U2_1.4 U2.U2_1.5 U2.U2_1.6 U2.U2_1.7 U2.U2_1.8 U2.U2_1.9 U2.U2_1.10 U2.U2_1.11 U2.U2_1.12 U2.U2_1.13 U2.U2_1.14 U3.7 U3_1.1 U3_1.2 U3_1.3 U3_1.4 U3_1.5 U3_1.6 U3_1.7 U3_1.8
copper on no net: | length 1119.2
  Top Layer w0.8: 298.577,112.395 298.577,113.284 303.657,118.364 303.657,120.015 ; 300.482,75.819 300.502,75.839 300.482,75.859 ; 303.002,75.839 303.022,75.819 ; 307.32,70.612 307.32,71.227 ; 307.975,76.073 308.102,75.946 308.102,75.819 ; 323.746,99.822 323.746,111.275 325.755,113.284 326.771,113.284 ; 326.644,91.059 327.787,91.059 330.073,93.345 330.073,113.919 328.168,115.824 326.771,115.824
  Top Layer w1: 316.357,120.015 322.453,120.015 324.104,118.364 326.771,118.364 ; 326.517,83.312 327.66,83.312 330.2,85.852 330.2,89.281 331.851,90.932 334.137,90.932 ; 331.724,90.805 331.724,109.855 332.613,110.744 334.391,110.744 ; 334.137,93.472 335.153,93.472 336.042,94.361 338.709,94.361 340.487,92.583 340.487,90.551 342.011,89.027 345.054,89.027 345.308,89.281 363.474,89.281 364.321,90.128 ; 334.391,108.204 335.153,108.204 342.011,101.346 345.694,101.346 345.821,101.473 345.948,101.473 346.202,101.727 362.204,101.727 363.135,102.658 365.633,102.658 ; 334.391,115.824 339.344,115.824 340.614,114.554 347.244,114.554 347.879,115.189 365.633,115.189 ; 344.678,103.378 344.932,103.378 346.583,105.029 358.902,105.029 361.611,107.738 365.633,107.738 ; 344.678,122.682 352.806,122.682 355.219,120.269 365.633,120.269 ; 345.186,97.282 345.186,96.774 346.456,95.504 365.337,95.504 365.633,95.208 ; 345.313,78.867 349.504,78.867 ; 349.377,78.867 353.187,82.677 365.633,82.677 ; 360.934,98.425 361.188,98.171 ; 361.188,90.128 365.633,90.128 ; 361.188,95.504 361.188,98.044 ; 361.188,110.998 361.188,107.338 361.199,107.326
  Top Layer w2: 358.521,73.025 358.521,77.851 360.807,80.137 365.633,80.137
  Bottom Layer w0.8: 290.576,90.404 290.576,96.52 ; 290.576,119.634 292.608,119.634 295.021,122.047 305.308,122.047 306.197,121.158 306.197,120.015 ; 295.402,84.074 295.402,88.265 297.648,90.511 301.792,90.511 303.022,89.281 303.022,83.439 ; 298.577,112.395 298.577,112.522 ; 299.697,105.029 299.697,107.927 301.117,109.347 301.117,112.395 ; 300.482,75.819 300.482,83.439 ; 300.502,75.839 303.002,75.839 ; 301.117,120.015 301.117,121.285 301.879,122.047 ; 303.022,75.819 303.022,72.41 304.82,70.612 ; 303.022,101.854 305.689,101.854 308.356,99.187 ; 303.657,112.395 303.657,111.506 307.086,108.077 314.813,108.077 315.087,107.803 ; 305.412,127.762 305.412,125.626 306.832,124.206 307.848,124.206 308.737,123.317 308.737,120.015 ; 305.562,83.439 305.562,81.661 307.467,79.756 311.15,79.756 315.468,84.074 318.897,84.074 320.04,82.931 320.04,77.978 ; 305.966,97.79 308.356,97.79 ; 306.197,112.395 306.197,111.379 307.467,110.109 321.437,110.109 322.072,110.744 327.914,110.744 329.438,109.22 329.438,87.757 327.533,85.852 326.517,85.852 ; 308.356,94.976 308.356,99.187 ; 309.372,87.884 308.102,86.614 308.102,83.439 311.912,83.439 312.42,82.931 ; 310.007,108.077 310.007,105.179 310.157,105.029 ; 311.277,120.015 311.277,123.571 311.912,124.206 314.833,124.206 315.811,125.184 315.811,127.701 316.106,127.996 321.818,127.996 ; 312.402,76.055 312.42,76.038 ; 313.286,95.885 315.214,95.885 316.992,94.107 316.992,87.884 ; 313.286,99.822 312.651,99.187 308.356,99.187 ; 313.817,120.015 313.817,120.904 315.341,122.428 321.31,122.428 324.104,119.634 324.104,117.348 325.628,115.824 328.041,115.824 ; 316.357,82.296 316.357,81.407 317.5,80.264 317.5,77.978 ; 321.691,117.455 321.691,117.856 ; 323.649,95.788 323.649,99.725 323.746,99.822 ; 323.746,95.885 322.326,94.465 322.326,89.408 323.342,88.392 326.517,88.392 ; 326.771,108.204 327.66,108.204 ; 347.98,84.582 347.98,112.709
  Bottom Layer w1: 290.576,117.094 289.687,117.094 288.163,115.57 288.163,102.108 292.481,97.79 295.506,97.79 ; 295.402,76.454 295.402,71.501 299.974,66.929 328.168,66.929 333.375,72.136 333.375,75.565 331.343,77.597 331.343,92.075 332.74,93.472 335.041,93.472 336.037,94.468 339.237,94.468 340.253,93.452 343.408,93.452 ; 295.402,101.854 291.846,101.854 290.576,103.124 290.576,112.014 292.227,112.014 296.164,115.951 313.436,115.951 316.357,118.872 316.357,120.015 319.659,120.015 321.691,117.983 321.691,117.455 ; 307.32,70.612 308.102,71.394 308.102,75.819 312.166,75.819 ; 311.912,75.692 323.596,75.692 324.485,76.581 324.485,82.296 325.501,83.312 328.295,83.312 328.95,82.657 328.95,73.914 ; 326.771,118.364 329.438,118.364 331.47,116.332 331.47,111.887 332.486,110.871 335.788,110.871 336.042,110.617 ; 327.787,118.364 328.95,119.527 328.95,127.254 ; 333.248,83.566 334.01,83.566 ; 334.137,80.772 334.137,79.629 334.899,78.867 337.566,78.867 ; 334.137,83.312 335.534,83.312 337.081,81.765 ; 334.137,85.852 338.074,85.852 338.602,85.324 344.063,85.324 344.663,84.724 344.79,84.724 351.917,77.597 365.633,77.597 ; 334.137,90.932 335.661,90.932 336.954,92.225 ; 334.137,96.774 334.137,96.012 334.391,96.012 335.661,97.282 337.566,97.282 ; 334.391,105.664 334.391,105.537 336.55,103.378 337.058,103.378 ; 334.391,108.204 335.153,108.204 337.566,105.791 341.864,105.791 343.408,107.335 ; 334.391,115.824 338.709,115.824 339.237,116.352 343.408,116.352 ; 334.391,118.364 337.716,118.364 337.82,118.26 340.129,118.26 340.721,118.852 343.408,118.852 ; 334.391,120.904 334.391,121.158 335.915,122.682 337.312,122.682 ; 335.788,110.744 337.82,108.712 337.82,107.8 ; 337.312,81.892 338.813,81.892 339.745,82.824 343.408,82.824 ; 337.312,92.352 337.312,92.329 338.689,90.952 343.408,90.952 ; 338.328,107.8 339.067,107.8 341.102,109.835 343.408,109.835 ; 338.351,118.618 338.709,118.26 ; 361.121,102.743 361.206,102.658 365.633,102.658
  Bottom Layer w2: 346.329,70.358 347.726,70.358 350.266,72.898 353.441,72.898 ; 353.06,118.618 355.219,118.618 355.346,118.491 ; 355.346,113.665 355.473,113.792 ; 358.1,121.325 358.1,128.27 ; 358.14,118.272 358.2,118.211 358.2,84.455 ; 358.2,90.128 365.633,90.128 ; 358.2,102.777 365.599,102.777 ; 361.121,102.711 361.188,102.777 ; 365.633,77.597 368.681,77.597 370.332,79.248 370.332,89.874 367.538,92.668 365.633,92.668 ; 365.633,80.137 356.997,80.137 355.346,81.788 355.346,119.507 356.87,121.031 358.775,121.031 362.077,117.729 365.633,117.729 ; 365.633,105.198 368.596,105.198 370.332,106.934 370.332,113.411 368.554,115.189 365.633,115.189
  other v1: 295.656,67.818 338.201,70.358 292.608,125.984 346.329,128.524
  other v2: 361.696,80.137

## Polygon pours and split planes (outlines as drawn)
no net on Top Layer "Top Layer-GND" (solid, remove dead copper, pour order 1000): 286.006,136.144 372.872,136.144 372.872,64.643 286.006,64.643 285.877,64.77 286.006,64.897
GND on Top Layer "Top Layer-GND" (solid, remove dead copper, pour order 1000): 196.598,136.398 283.464,136.398 283.464,64.897 196.598,64.897 196.469,65.024 196.598,65.151
no net on Bottom Layer "Bottom Layer-GND" (solid, remove dead copper, pour order 1001): 285.877,136.144 372.999,136.144 372.999,64.516 286.005,64.516 285.877,64.643
GND on Bottom Layer "Bottom Layer-GND" (solid, remove dead copper, pour order 1001): 196.469,136.398 283.591,136.398 283.591,64.77 196.597,64.77 196.469,64.897

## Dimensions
192.532,52.197 to 393.827,57.912 on Top Layer
409.321,61.008 to 204.597,211.122 on Top Layer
